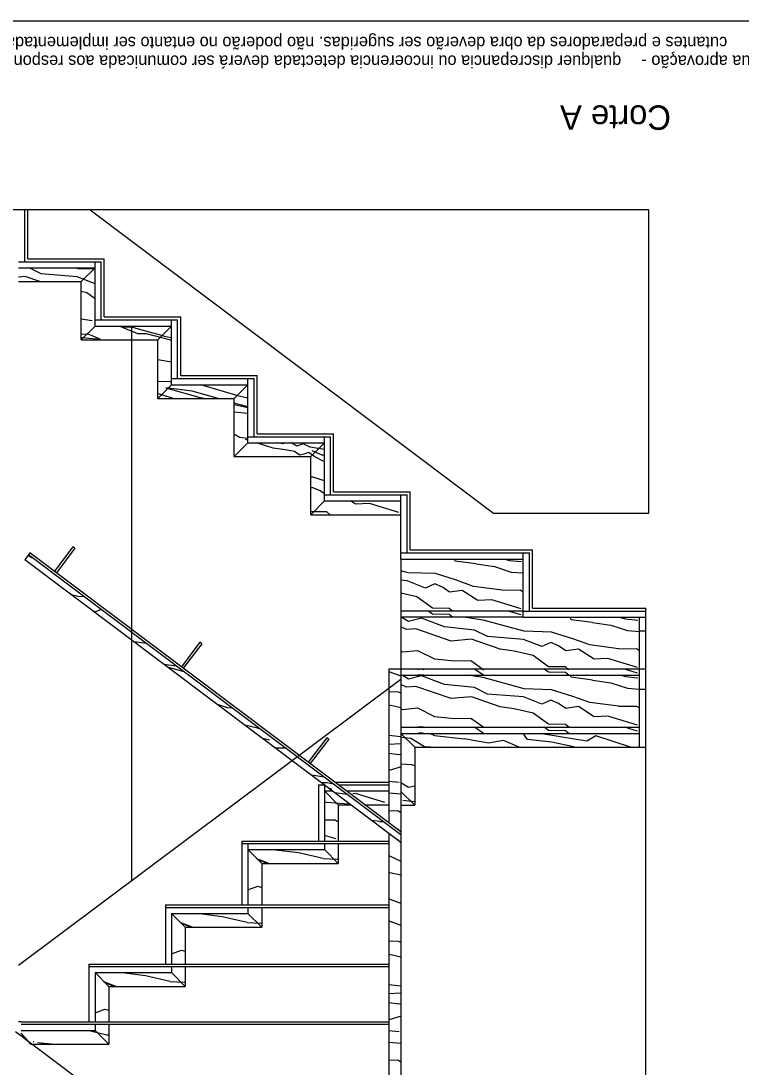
# Model space of a CAD drawing. Extents: x 1295.6 to 1307.2, y -287.2 to -277.8.
# Drawn here: x 1299.697 to 1302.052, y -281.259 to -277.838 of the extents above; entities that cross this region are included whole.
import ezdxf

# ---------------------------------------------------------------- set-up
doc = ezdxf.new("R2010")
doc.units = 0
for name, color, linetype in [('Level 1', 7, 'Continuous'), ('Level 13', 7, 'Continuous'), ('Level 2', 7, 'Continuous'), ('Level 31', 7, 'Continuous'), ('Level 4', 7, 'Continuous'), ('Level 60', 7, 'Continuous'), ('Level 62', 7, 'Continuous')]:
    doc.layers.add(name, color=color, linetype=linetype)

msp = doc.modelspace()

# ---------------------------------------------------------------- linework, layer by layer
at = {"layer": 'Level 1'}
for p, q in [((1301.7497, -278.45564), (1299.22246, -278.45564)), ((1299.7097, -278.62564), (1299.7097, -278.45564)), ((1299.7197, -278.61564), (1299.7197, -278.45564)), ((1299.9233, -278.45564), (1301.24246, -279.44764)), ((1301.7497, -279.44764), (1301.7497, -278.45564)), ((1299.6897, -278.62564), (1299.9597, -278.62564)), ((1299.7197, -278.61564), (1299.9697, -278.61564)), ((1299.9397, -278.83564), (1299.9397, -278.62564)), ((1299.9597, -278.81564), (1299.9597, -278.62564)), ((1299.9697, -278.80564), (1299.9697, -278.61564)), ((1299.6897, -278.64564), (1299.9397, -278.64564)), ((1299.9397, -278.81564), (1300.2097, -278.81564)), ((1299.9697, -278.80564), (1300.2197, -278.80564)), ((1300.1897, -279.02764), (1300.1897, -278.81564)), ((1300.2097, -279.00764), (1300.2097, -278.81564)), ((1300.2197, -278.99764), (1300.2197, -278.80564)), ((1299.9397, -278.83564), (1300.1897, -278.83564)), ((1300.2197, -278.99764), (1300.4697, -278.99764)), ((1300.4697, -279.18764), (1300.4697, -278.99764)), ((1300.1897, -279.00764), (1300.4597, -279.00764)), ((1300.1897, -279.02764), (1300.4397, -279.02764)), ((1300.4397, -279.21764), (1300.4397, -279.00764)), ((1300.4597, -279.19764), (1300.4597, -279.00764)), ((1300.4397, -279.19764), (1300.7097, -279.19764)), ((1300.4697, -279.18764), (1300.7197, -279.18764)), ((1300.6897, -279.40764), (1300.6897, -279.19764)), ((1300.7097, -279.38764), (1300.7097, -279.19764)), ((1300.7197, -279.37764), (1300.7197, -279.18764)), ((1300.4397, -279.21764), (1300.6897, -279.21764)), ((1300.7197, -279.37764), (1300.9697, -279.37764)), ((1300.9697, -279.56764), (1300.9697, -279.37764)), ((1300.6897, -279.38764), (1300.9597, -279.38764)), ((1300.6897, -279.40764), (1300.9397, -279.40764)), ((1300.9397, -279.59764), (1300.9397, -279.38764)), ((1300.9597, -279.57764), (1300.9597, -279.38764)), ((1301.24246, -279.44764), (1301.7497, -279.44764)), ((1300.9397, -279.57764), (1301.3597, -279.57764)), ((1300.9697, -279.56764), (1301.3697, -279.56764)), ((1301.3397, -279.78764), (1301.3397, -279.57764)), ((1301.3597, -279.76764), (1301.3597, -279.57764)), ((1301.3697, -279.75764), (1301.3697, -279.56764)), ((1300.9397, -279.59764), (1301.3397, -279.59764)), ((1301.3397, -279.76764), (1301.7397, -279.76764)), ((1301.3397, -279.78764), (1301.7397, -279.78764)), ((1301.3697, -279.75764), (1301.7397, -279.75764)), ((1301.7197, -279.83264), (1301.7197, -279.78764)), ((1301.7397, -282.31764), (1301.7397, -279.75764)), ((1301.7197, -279.83264), (1301.7397, -279.83264)), ((1299.6977, -281.11064), (1299.6897, -281.11064)), ((1299.6797, -281.14245), (1301.24246, -282.31764))]:
    msp.add_line(p, q, dxfattribs=at)
at = {"layer": 'Level 13'}
msp.add_line((1299.7297, -281.18364), (1299.6977, -281.14764), dxfattribs=at)
for points in [[(1299.9397, -278.69781), (1299.8816, -278.67474), (1299.76365, -278.66513), (1299.72409, -278.64564)], [(1299.9397, -278.6499), (1299.88409, -278.64833), (1299.8743, -278.64564)], [(1299.75883, -278.69064), (1299.71102, -278.6739), (1299.6897, -278.67591)], [(1299.9397, -278.74684), (1299.91262, -278.72742), (1299.8947, -278.72322)], [(1299.8947, -278.81168), (1299.93032, -278.81736)], [(1299.8947, -278.87254), (1299.8966, -278.87293), (1299.95669, -278.87838), (1299.91729, -278.86274), (1299.8947, -278.86368)], [(1300.02099, -278.83564), (1300.07836, -278.86066), (1300.10676, -278.86017), (1300.16093, -278.87377)], [(1300.1656, -278.86909), (1300.08141, -278.84565), (1300.06024, -278.83892), (1300.03564, -278.83961), (1300.02509, -278.83564)], [(1300.16093, -278.87377), (1300.1897, -278.88214)], [(1300.1656, -278.86909), (1300.1897, -278.8727)], [(1300.1897, -278.95393), (1300.1447, -278.94584)], [(1300.1897, -279.01822), (1300.1447, -279.01669)], [(1300.34231, -279.07264), (1300.25726, -279.04848), (1300.17076, -279.03799), (1300.27942, -279.06826), (1300.30049, -279.07264)], [(1300.4397, -279.07156), (1300.41136, -279.0648), (1300.28567, -279.02764)], [(1300.1447, -279.05616), (1300.15688, -279.05973), (1300.19727, -279.07264)], [(1300.4397, -279.09948), (1300.3947, -279.08744)], [(1300.3947, -279.09223), (1300.4397, -279.10158)], [(1300.3947, -279.11593), (1300.4397, -279.12078)], [(1300.4397, -279.20299), (1300.41182, -279.20066), (1300.39765, -279.19124), (1300.3947, -279.19209)], [(1300.4397, -279.20903), (1300.43205, -279.20664)], [(1300.6897, -279.27879), (1300.68736, -279.27905), (1300.65795, -279.26388), (1300.63853, -279.24922), (1300.6226, -279.25467), (1300.60904, -279.25773), (1300.59225, -279.24569), (1300.56083, -279.24041), (1300.52192, -279.23475), (1300.46722, -279.21764)], [(1300.55925, -279.21764), (1300.55366, -279.22136), (1300.53605, -279.21764)], [(1300.6897, -279.23917), (1300.64267, -279.23197), (1300.61968, -279.22087), (1300.59887, -279.22857), (1300.58059, -279.21764)], [(1300.6897, -279.25743), (1300.68256, -279.25763), (1300.64947, -279.24353)], [(1300.6897, -279.3418), (1300.65209, -279.32966), (1300.6447, -279.32945)], [(1300.6897, -279.38447), (1300.67514, -279.37438), (1300.64998, -279.36366), (1300.6447, -279.3661)], [(1300.93244, -279.44538), (1300.83638, -279.41643), (1300.79098, -279.41798), (1300.77496, -279.40764)], [(1300.70859, -279.45264), (1300.69751, -279.4437), (1300.6447, -279.4429)], [(1299.73547, -279.59378), (1299.73299, -279.59357), (1299.72075, -279.58543)], [(1301.18561, -279.61355), (1301.11652, -279.60421), (1301.11363, -279.59764)], [(1301.18561, -279.61355), (1301.24597, -279.62218), (1301.29991, -279.64), (1301.3397, -279.64298)], [(1301.27914, -279.59764), (1301.29423, -279.60182), (1301.33422, -279.60569)], [(1301.27096, -279.6989), (1301.17733, -279.68683), (1301.12141, -279.66703), (1301.05209, -279.64466), (1300.96291, -279.64216), (1300.9397, -279.63578)], [(1301.33244, -279.76038), (1301.23638, -279.73143), (1301.19098, -279.73298), (1301.1401, -279.70015), (1301.09868, -279.70569), (1301.07514, -279.68938), (1301.04998, -279.67866), (1301.02034, -279.69235), (1300.96042, -279.66856), (1300.9397, -279.66687)], [(1299.90417, -279.72064), (1299.88409, -279.72007), (1299.86212, -279.71403)], [(1301.10859, -279.76764), (1301.09751, -279.7587), (1301.04251, -279.75787), (1300.99144, -279.72125), (1300.9397, -279.70911)], [(1301.27096, -279.6989), (1301.32931, -279.69829), (1301.3397, -279.70441)], [(1299.95927, -279.76207), (1299.94151, -279.77027), (1299.93174, -279.76639)], [(1301.71244, -279.95205), (1301.61638, -279.9231), (1301.57098, -279.92465), (1301.5201, -279.89182), (1301.47868, -279.89736), (1301.45514, -279.88105), (1301.42998, -279.87033), (1301.40034, -279.88402), (1301.34042, -279.86023), (1301.22247, -279.85062), (1301.17974, -279.82957), (1301.08259, -279.8191), (1301.00729, -279.79075), (1300.96426, -279.80189), (1300.94093, -279.78764)], [(1301.10859, -279.78764), (1301.09751, -279.7787), (1301.04251, -279.77787), (1301.02824, -279.76764)], [(1301.65096, -279.89057), (1301.55733, -279.8785), (1301.50141, -279.8587), (1301.43209, -279.83633), (1301.34291, -279.83383), (1301.20845, -279.79687), (1301.14422, -279.78764)], [(1301.33244, -279.78038), (1301.29017, -279.76764)], [(1301.56561, -279.80522), (1301.49652, -279.79588), (1301.49289, -279.78764)], [(1301.65311, -279.78764), (1301.67423, -279.79349), (1301.71422, -279.79736)], [(1301.48859, -279.95931), (1301.47751, -279.95037), (1301.42251, -279.94954), (1301.37144, -279.91292), (1301.3101, -279.89853), (1301.26432, -279.89247), (1301.16984, -279.8594), (1301.10382, -279.86562), (1300.98817, -279.82581), (1300.95797, -279.82811), (1300.9397, -279.8194)], [(1301.56561, -279.80522), (1301.62597, -279.81385), (1301.67991, -279.83167), (1301.7197, -279.83465)], [(1300.10717, -279.87329), (1300.06722, -279.86827)], [(1301.65096, -279.89057), (1301.70931, -279.88996), (1301.7197, -279.89608)], [(1300.9397, -279.89908), (1300.94453, -279.90134), (1300.99354, -279.89619), (1301.04984, -279.92359), (1301.11461, -279.93057), (1301.16761, -279.9294), (1301.21076, -279.95931)], [(1300.1656, -279.94083), (1300.16259, -279.93999)], [(1300.1656, -279.94083), (1300.20479, -279.9467)], [(1300.17561, -279.94978), (1300.22987, -279.96556)], [(1301.01415, -279.95931), (1301.00414, -279.95734), (1300.99495, -279.95931)], [(1301.18046, -279.95664), (1301.21076, -279.97764)], [(1301.48859, -279.97764), (1301.47751, -279.9687), (1301.42251, -279.96787), (1301.40685, -279.95664)], [(1301.71244, -279.97038), (1301.66685, -279.95664)], [(1300.8997, -279.96496), (1300.9397, -279.97947)], [(1301.71244, -280.14038), (1301.61638, -280.11143), (1301.57098, -280.11298), (1301.5201, -280.08015), (1301.47868, -280.08569), (1301.45514, -280.06938), (1301.42998, -280.05866), (1301.40034, -280.07235), (1301.34042, -280.04856), (1301.22247, -280.03895), (1301.17974, -280.0179), (1301.08259, -280.00743), (1301.00729, -279.97908), (1300.96426, -279.99022), (1300.94366, -279.97764)], [(1301.01415, -279.97764), (1301.00414, -279.97567), (1300.99495, -279.97764)], [(1301.65096, -280.0789), (1301.55733, -280.06683), (1301.50141, -280.04703), (1301.43209, -280.02466), (1301.34291, -280.02216), (1301.20845, -279.9852), (1301.15585, -279.97764)], [(1301.56561, -279.99355), (1301.49652, -279.98421), (1301.49363, -279.97764)], [(1301.56561, -279.99355), (1301.62597, -280.00218), (1301.67991, -280.02), (1301.7197, -280.02298)], [(1301.65914, -279.97764), (1301.67423, -279.98182), (1301.71422, -279.98569)], [(1301.48859, -280.14764), (1301.47751, -280.1387), (1301.42251, -280.13787), (1301.37144, -280.10125), (1301.3101, -280.08686), (1301.26432, -280.0808), (1301.16984, -280.04773), (1301.10382, -280.05395), (1300.98817, -280.01414), (1300.95797, -280.01644), (1300.9397, -280.00773)], [(1300.8997, -280.03084), (1300.93101, -280.03166), (1300.9397, -280.03481)], [(1300.38864, -280.08496), (1300.37259, -280.08353), (1300.33985, -280.07329)], [(1300.9397, -280.08374), (1300.91625, -280.07829), (1300.8997, -280.07503)], [(1300.9397, -280.08741), (1300.94453, -280.08967), (1300.99354, -280.08452), (1301.04984, -280.11192), (1301.11461, -280.1189), (1301.16761, -280.11773), (1301.21076, -280.14764)], [(1301.65096, -280.0789), (1301.70931, -280.07829), (1301.7197, -280.08441)], [(1300.48144, -280.15474), (1300.47062, -280.15067), (1300.42981, -280.14094)], [(1301.01415, -280.14764), (1301.00414, -280.14567), (1300.99495, -280.14764)], [(1301.01415, -280.16764), (1301.00414, -280.16567), (1300.99495, -280.16764)], [(1301.18191, -280.14764), (1301.21076, -280.16764)], [(1301.48859, -280.16764), (1301.47751, -280.1587), (1301.42251, -280.15787), (1301.40824, -280.14764)], [(1301.71244, -280.16038), (1301.67017, -280.14764)], [(1300.48554, -280.18285), (1300.50733, -280.18738)], [(1300.50995, -280.19), (1300.48683, -280.18382)], [(1300.8997, -280.17305), (1300.9397, -280.17723)], [(1301.03606, -280.21264), (1301.01668, -280.21123), (1300.97177, -280.18438), (1300.9397, -280.18111)], [(1301.03569, -280.16764), (1301.04899, -280.17492), (1301.14622, -280.18533)], [(1301.32578, -280.21264), (1301.27448, -280.19093), (1301.22565, -280.19989), (1301.14622, -280.18533)], [(1301.50622, -280.21264), (1301.50478, -280.21176), (1301.43204, -280.1968), (1301.35388, -280.18727), (1301.33975, -280.16951), (1301.32802, -280.16764)], [(1301.68995, -280.21264), (1301.5769, -280.17552), (1301.54744, -280.19302), (1301.40034, -280.16872), (1301.39795, -280.16764)], [(1300.52785, -280.21467), (1300.56194, -280.21529)], [(1300.9397, -280.20183), (1300.8997, -280.20387)], [(1300.8997, -280.23217), (1300.93353, -280.23642), (1300.9397, -280.23508)], [(1300.9397, -280.26719), (1300.97408, -280.26976), (1300.9847, -280.27238)], [(1300.9397, -280.27862), (1300.93558, -280.2782), (1300.90575, -280.28811), (1300.8997, -280.28681)], [(1300.68895, -280.3108), (1300.64718, -280.3044)], [(1300.71864, -280.33312), (1300.69874, -280.32891), (1300.68256, -280.32937), (1300.67753, -280.32723)], [(1300.8997, -280.32407), (1300.93422, -280.32741)], [(1300.9397, -280.32862), (1300.96443, -280.34319), (1300.9847, -280.33952)], [(1300.71362, -280.35437), (1300.71091, -280.34821), (1300.70613, -280.34873)], [(1300.70804, -280.35564), (1300.71054, -280.35588)], [(1300.76422, -280.3674), (1300.72366, -280.36191)], [(1300.88724, -280.39338), (1300.79118, -280.36443), (1300.78235, -280.36473)], [(1300.8997, -280.36165), (1300.89991, -280.36172), (1300.9397, -280.3647)], [(1300.6897, -280.39028), (1300.69491, -280.392), (1300.76908, -280.39755), (1300.77151, -280.39815)], [(1300.94558, -280.38597), (1300.9847, -280.39009)], [(1300.8997, -280.42032), (1300.92931, -280.42001), (1300.9397, -280.42613)], [(1300.6897, -280.45065), (1300.72431, -280.45029), (1300.7347, -280.45641)], [(1300.87096, -280.45564), (1300.8436, -280.45211)], [(1300.87096, -280.45564), (1300.88142, -280.45553)], [(1300.72744, -280.51238), (1300.6897, -280.50101)], [(1300.9067, -280.4992), (1300.8997, -280.49678)], [(1300.93244, -280.4821), (1300.92844, -280.4809)], [(1300.93244, -280.51712), (1300.92844, -280.51592)], [(1300.6857, -280.57664), (1300.60437, -280.55831), (1300.53, -280.54896), (1300.52836, -280.54764)], [(1300.6857, -280.57664), (1300.73131, -280.57924), (1300.7347, -280.58016)], [(1300.8997, -280.56635), (1300.9397, -280.58583)], [(1300.50736, -280.59264), (1300.46891, -280.57816), (1300.5021, -280.59264)], [(1300.9397, -280.63117), (1300.90296, -280.62394), (1300.8997, -280.62464)], [(1300.4397, -280.67923), (1300.47141, -280.66734), (1300.4847, -280.67102)], [(1300.8997, -280.70836), (1300.9397, -280.7223)], [(1300.4367, -280.78564), (1300.35537, -280.76731), (1300.281, -280.75796), (1300.27936, -280.75664)], [(1300.8997, -280.78033), (1300.9397, -280.79484)], [(1300.25836, -280.80164), (1300.21991, -280.78716), (1300.2531, -280.80164)], [(1300.4367, -280.78564), (1300.48231, -280.78824), (1300.4857, -280.78916)], [(1300.8997, -280.84621), (1300.93101, -280.84703), (1300.9397, -280.85018)], [(1300.1897, -280.88861), (1300.22241, -280.87634), (1300.2347, -280.87974)], [(1300.9397, -280.89911), (1300.91625, -280.89366), (1300.8997, -280.8904)], [(1300.1857, -280.97864), (1300.10437, -280.96031), (1300.03, -280.95096), (1300.02836, -280.94964)], [(1300.00736, -280.99464), (1299.96891, -280.98016), (1300.0021, -280.99464)], [(1300.1857, -280.97864), (1300.23131, -280.98124), (1300.2347, -280.98216)], [(1300.8997, -280.98842), (1300.9397, -280.9926)], [(1300.9397, -281.0172), (1300.8997, -281.01924)], [(1300.8997, -281.04754), (1300.93353, -281.05179), (1300.9397, -281.05045)], [(1299.9397, -281.08123), (1299.97141, -281.06934), (1299.9847, -281.07302)], [(1300.9397, -281.09399), (1300.93558, -281.09357), (1300.90575, -281.10348), (1300.8997, -281.10218)], [(1299.9847, -281.15459), (1299.97811, -281.15385), (1299.92482, -281.14164)], [(1300.8997, -281.13944), (1300.93422, -281.14278)], [(1299.73944, -281.17638), (1299.73742, -281.17577)], [(1299.75258, -281.17776), (1299.80835, -281.18364)], [(1300.8997, -281.17702), (1300.89991, -281.17709), (1300.9397, -281.18007)], [(1300.8997, -281.23569), (1300.92931, -281.23538), (1300.9397, -281.2415)]]:
    msp.add_lwpolyline(points, dxfattribs=at)
at = {"layer": 'Level 2'}
for p, q in [((1299.8947, -278.69064), (1299.9397, -278.64564)), ((1299.6897, -278.69064), (1299.8947, -278.69064)), ((1299.8947, -278.88064), (1299.8947, -278.69064)), ((1299.8947, -278.88064), (1299.9397, -278.83564)), ((1300.1447, -278.88064), (1300.1897, -278.83564)), ((1299.8947, -278.88064), (1300.1447, -278.88064)), ((1300.1447, -279.07264), (1300.1447, -278.88064)), ((1300.1447, -279.07264), (1300.1897, -279.02764)), ((1300.3947, -279.07264), (1300.4397, -279.02764)), ((1300.1447, -279.07264), (1300.3947, -279.07264)), ((1300.3947, -279.26264), (1300.3947, -279.07264)), ((1300.3947, -279.26264), (1300.4397, -279.21764)), ((1300.6447, -279.26264), (1300.6897, -279.21764)), ((1300.3947, -279.26264), (1300.6447, -279.26264)), ((1300.6447, -279.45264), (1300.6447, -279.26264)), ((1300.6447, -279.45264), (1300.6897, -279.40764)), ((1300.6447, -279.45264), (1300.9397, -279.45264)), ((1299.72686, -279.5773), (1299.71004, -279.59967)), ((1300.9397, -280.49936), (1299.72206, -279.58369)), ((1300.9397, -280.48936), (1299.72686, -279.5773)), ((1299.8669, -279.5575), (1299.80678, -279.6374)), ((1299.8733, -279.56231), (1299.81318, -279.64221)), ((1299.8733, -279.56231), (1299.8669, -279.5575)), ((1300.9397, -280.52438), (1299.71004, -279.59967)), ((1300.9397, -279.59764), (1300.9397, -280.35764)), ((1301.3397, -279.76764), (1300.9397, -279.76764)), ((1301.3397, -279.78764), (1300.9397, -279.78764)), ((1300.28198, -279.86962), (1300.22186, -279.94952)), ((1300.28836, -279.87443), (1300.22824, -279.95433)), ((1300.28836, -279.87443), (1300.28198, -279.86962)), ((1300.8997, -279.95664), (1301.7397, -279.95664)), ((1300.8997, -279.95664), (1300.8997, -280.45928)), ((1300.9397, -279.97764), (1301.7197, -279.97764)), ((1300.9397, -280.14764), (1301.7197, -280.14764)), ((1300.69704, -280.18176), (1300.63692, -280.26166)), ((1300.70342, -280.18657), (1300.6433, -280.26647)), ((1300.70342, -280.18657), (1300.69704, -280.18176)), ((1300.9397, -280.16764), (1301.7197, -280.16764)), ((1300.6697, -280.33564), (1300.6697, -280.51964)), ((1300.6697, -280.33564), (1300.68872, -280.33564)), ((1300.6897, -280.33564), (1300.6897, -280.51964)), ((1300.72332, -280.32664), (1300.8997, -280.32664)), ((1300.73529, -280.33564), (1300.8997, -280.33564)), ((1300.9397, -280.32664), (1300.9397, -281.30473)), ((1300.6897, -280.35564), (1300.71531, -280.35564)), ((1300.76188, -280.35564), (1300.8997, -280.35564)), ((1300.8997, -280.4943), (1300.8997, -281.33431)), ((1300.4197, -280.51964), (1300.8997, -280.51964)), ((1300.4197, -280.51964), (1300.4197, -280.72864)), ((1300.4197, -280.52764), (1300.6897, -280.52764)), ((1300.4397, -280.52764), (1300.8997, -280.52764)), ((1300.4397, -280.52764), (1300.4397, -280.72864)), ((1300.6897, -280.52764), (1300.6897, -280.54764)), ((1300.4397, -280.54764), (1300.6897, -280.54764)), ((1300.1697, -280.72864), (1300.8997, -280.72864)), ((1300.1697, -280.72864), (1300.1697, -280.92164)), ((1300.1697, -280.73664), (1300.4397, -280.73664)), ((1300.2097, -280.73664), (1300.8997, -280.73664)), ((1300.4397, -280.73664), (1300.4397, -280.75664)), ((1300.1897, -280.75664), (1300.4397, -280.75664)), ((1300.1897, -280.75664), (1300.1897, -280.92164)), ((1299.9197, -280.92164), (1300.1697, -280.92164)), ((1299.9197, -280.92164), (1299.9197, -281.11064)), ((1299.9197, -280.92964), (1300.1897, -280.92964)), ((1299.9397, -280.94964), (1300.1897, -280.94964)), ((1299.9397, -280.94964), (1299.9397, -281.11064)), ((1299.9597, -280.92164), (1300.8997, -280.92164)), ((1299.9597, -280.92964), (1300.8997, -280.92964)), ((1300.1897, -280.92964), (1300.1897, -280.94964)), ((1299.6977, -281.11064), (1300.8997, -281.11064)), ((1299.6977, -281.11864), (1299.9397, -281.11864)), ((1299.7097, -281.11864), (1300.8997, -281.11864)), ((1299.9397, -281.11864), (1299.9397, -281.13864)), ((1299.6977, -281.13864), (1299.9397, -281.13864))]:
    msp.add_line(p, q, dxfattribs=at)
at = {"layer": 'Level 31'}
for p, q in [((1301.7197, -280.21264), (1301.7197, -279.83264)), ((1301.7197, -280.02264), (1301.7397, -280.02264)), ((1300.9847, -280.21264), (1300.9397, -280.16764)), ((1300.9847, -280.21264), (1301.7397, -280.21264)), ((1300.9847, -280.21464), (1300.9847, -280.40264)), ((1300.7347, -280.40064), (1300.6897, -280.35564)), ((1300.9847, -280.40264), (1300.9397, -280.35764)), ((1300.7347, -280.40064), (1300.7347, -280.51964)), ((1300.7347, -280.40064), (1300.77515, -280.40064)), ((1300.82172, -280.40064), (1300.8997, -280.40064)), ((1300.9397, -280.40264), (1300.9847, -280.40264)), ((1300.7347, -280.52764), (1300.7347, -280.59264)), ((1300.4847, -280.59264), (1300.4397, -280.54764)), ((1300.7347, -280.59264), (1300.6897, -280.54764)), ((1300.4847, -280.59264), (1300.7347, -280.59264)), ((1300.4847, -280.59264), (1300.4847, -280.72864)), ((1300.4847, -280.73664), (1300.4847, -280.80164)), ((1300.2347, -280.80164), (1300.1897, -280.75664)), ((1300.4847, -280.80164), (1300.4397, -280.75664)), ((1300.2347, -280.80164), (1300.4847, -280.80164)), ((1300.2347, -280.80164), (1300.2347, -280.92164)), ((1299.9847, -280.99464), (1299.9397, -280.94964)), ((1300.2347, -280.99464), (1300.1897, -280.94964)), ((1300.2347, -280.92964), (1300.2347, -280.99464)), ((1299.9847, -280.99364), (1299.9847, -281.11064)), ((1299.9847, -280.99464), (1300.2347, -280.99464)), ((1299.9847, -281.11864), (1299.9847, -281.18364)), ((1299.9847, -281.18364), (1299.9397, -281.13864)), ((1299.7297, -281.18364), (1299.9847, -281.18364))]:
    msp.add_line(p, q, dxfattribs=at)
at = {"layer": 'Level 4'}
for p, q in [((1300.0597, -280.64773), (1300.0597, -278.83564)), ((1299.6897, -280.92564), (1300.9397, -279.98997))]:
    msp.add_line(p, q, dxfattribs=at)
at = {"layer": 'Level 62'}
msp.add_lwpolyline([(1307.19356, -277.83814), (1307.19356, -287.18414), (1295.59396, -287.18414), (1295.59396, -277.83814)], close=True, dxfattribs=at)

# ---------------------------------------------------------------- texts
at = {"layer": 'Level 60'}
for s, height, rotation, p in [('cutantes e preparadores da obra deverão ser sugeridas. não poderão no entanto ser implementadas sem o consentimento expresso dos responsáveis pela arquitectura', 0.0399996, 180, (1302.00637, -277.89014)), ('qualquer discrepancia ou incoerencia detectada deverá ser comunicada aos responsáveis pela arquitectura com o objectivo de ser analizada e corrigida -', 0.0399996, 180, (1301.65977, -277.95114)), ('os desenhos de preparação de obra deverão ser fornecidos ao projectista para sua aprovação -', 0.0399996, 180, (1303.99717, -277.95114)), ('Corte A', 0.08, 180.00001, (1301.82233, -278.11418))]:
    msp.add_text(s, height=height, rotation=rotation, dxfattribs=at).set_placement(p)

doc.saveas('drawing.dxf')
